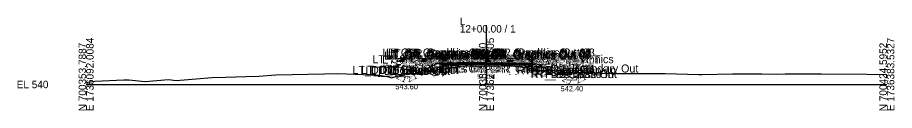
# Model space of a CAD drawing. Extents: x -26 to 697, y -10 to 2642.
# Drawn here: x -25.7 to 302.8, y 790.3 to 825 of the extents above; entities that cross this region are included whole.
import ezdxf

# ---------------------------------------------------------------- set-up
doc = ezdxf.new("R2010")
doc.units = 0
for name, color, linetype in [('Default', 7, 'Continuous'), ('Exist Cross Section Cell', 7, 'Continuous'), ('Exist XS Center Line Elevation Label', 7, 'Continuous'), ('Exist XS Ground Line', 7, 'Continuous'), ('Prop CMT Ditch DDE', 7, 'Continuous'), ('Prop CMT Guardrail Graphics', 7, 'Continuous'), ('Prop CMT Pvmt Course 1', 7, 'Continuous'), ('Prop CMT Pvmt Course 2', 7, 'Continuous'), ('Prop CMT Pvmt Surface', 7, 'Continuous'), ('Prop CMT Pvmt Surface Shoulder', 7, 'Continuous'), ('Prop CMT Shld Paved Course 1', 7, 'Continuous'), ('Prop CMT Shld Paved Course 2', 7, 'Continuous'), ('Prop CMT Slope Grass', 7, 'Continuous'), ('Prop CMT Subgrade Earthwork', 7, 'Continuous'), ('Prop XS Ditch Slope Text', 7, 'Continuous'), ('Prop XS Ditch Standard Text', 7, 'Continuous'), ('Prop XS SE Text', 7, 'Continuous'), ('Prop XS Side Slope Text', 7, 'Continuous')]:
    doc.layers.add(name, color=color, linetype=linetype)

msp = doc.modelspace()

# ---------------------------------------------------------------- linework, layer by layer
at = {"layer": 'Exist Cross Section Cell'}
for p, q in [((150, 800), (150, 822.2)), ((0, 800), (150, 800)), ((150, 800), (300, 800))]:
    msp.add_line(p, q, dxfattribs=at)
at = {"layer": 'Exist XS Ground Line'}
msp.add_lwpolyline([(0, 800.77), (3.26, 801.24), (14.09, 801.75), (16, 801.69), (22.08, 801.13), (30.89, 801.8), (33.77, 801.54), (41.24, 802.11), (47.09, 802.64), (52.16, 802.75), (59.97, 802.96), (64.67, 803.13), (71.03, 803.57), (89.36, 804), (94.3, 804.07), (97.52, 804), (109.9, 803.46), (113.46, 802.82), (114.25, 802.49), (120.37, 804.15), (121.19, 804.13), (124.03, 804.03), (124.71, 804.28), (125.87, 804.63), (128.83, 805.32), (132.7, 805.7), (134.61, 805.98), (136.73, 806.28), (140.54, 806.89), (144.86, 806.95), (149.69, 807), (150, 807), (159.67, 806.94), (160, 806.94), (160.56, 806.87), (164.49, 806.35), (167.73, 805.86), (170.77, 805.15), (172.35, 804.78), (173.05, 804.61), (175.25, 803.23), (177.12, 804.51), (181.98, 804.47), (188.77, 804.47), (192.71, 804.27), (198.65, 804.08), (209.91, 804.06), (216.94, 804.09), (229.51, 803.71), (230.75, 803.7), (242.11, 803.95), (253.15, 803.95), (258.48, 803.89), (261.9, 804), (271.23, 803.95), (274.36, 803.98), (275.49, 803.99), (292.51, 803.83), (300, 803.76)], dxfattribs=at)
at = {"layer": 'Prop CMT Ditch DDE'}
for points in [[(120.17, 803.6), (119.48, 803.94)], [(123.92, 804.03), (120.92, 803.97), (120.17, 803.6)], [(120.17, 803.6), (120.17, 803.6)], [(176.32, 803.91), (179.32, 803.85), (182.23, 802.4)], [(182.23, 802.4), (186.37, 804.47)], [(182.23, 802.4), (182.23, 802.4)]]:
    msp.add_lwpolyline(points, dxfattribs=at)
at = {"layer": 'Prop CMT Guardrail Graphics'}
for points in [[(132.65, 804.44), (132.65, 810.44)], [(132.65, 810.44), (133.98, 810.44), (134.25, 810.15)], [(134.25, 809.57), (133.98, 809.27), (133.31, 809.27)], [(133.31, 809.27), (133.31, 804.44)], [(134.25, 810.15), (133.98, 809.86)], [(133.98, 809.86), (134.25, 809.57)], [(167.35, 810.44), (166.02, 810.44), (165.75, 810.15)], [(165.75, 810.15), (166.02, 809.86)], [(166.02, 809.86), (165.75, 809.57)], [(165.75, 809.57), (166.02, 809.27), (166.69, 809.27)], [(166.69, 809.27), (166.69, 804.44)], [(167.35, 804.44), (167.35, 810.44)], [(133.31, 804.44), (132.65, 804.44)], [(166.69, 804.44), (167.35, 804.44)]]:
    msp.add_lwpolyline(points, dxfattribs=at)
at = {"layer": 'Prop CMT Pvmt Course 1'}
for points in [[(150, 808.26), (139, 808.04)], [(150, 808.05), (150, 808.26)], [(150, 808.26), (161, 808.04)], [(150, 808.05), (150, 808.26)], [(139, 807.83), (150, 808.05)], [(139, 808.04), (139, 807.83)], [(161, 807.83), (150, 808.05)], [(161, 808.04), (161, 807.83)]]:
    msp.add_lwpolyline(points, dxfattribs=at)
msp.add_lwpolyline([(150, 808.05), (150, 808.15), (150, 808.15), (150, 808.05)], close=True, dxfattribs=at)
msp.add_lwpolyline([(150, 808.05), (150, 808.15), (150, 808.15), (150, 808.05)], close=True, dxfattribs=at)
at = {"layer": 'Prop CMT Pvmt Course 2'}
for points in [[(150, 808.05), (139, 807.83)], [(139, 807.83), (139, 807.37)], [(139, 807.37), (150, 807.59)], [(150, 807.59), (150, 808.05)], [(150, 807.59), (150, 808.05)], [(150, 808.05), (161, 807.83)], [(161, 807.37), (150, 807.59)], [(161, 807.83), (161, 807.37)]]:
    msp.add_lwpolyline(points, dxfattribs=at)
at = {"layer": 'Prop CMT Pvmt Surface'}
for points in [[(150, 808.26), (139, 808.04)], [(150, 808.26), (161, 808.04)]]:
    msp.add_lwpolyline(points, dxfattribs=at)
at = {"layer": 'Prop CMT Pvmt Surface Shoulder'}
for points in [[(139, 808.04), (134.26, 807.94)], [(161, 808.04), (165.74, 807.94)]]:
    msp.add_lwpolyline(points, dxfattribs=at)
at = {"layer": 'Prop CMT Shld Paved Course 1'}
for points in [[(139, 808.04), (134.26, 807.94), (134.05, 807.73)], [(134.05, 807.73), (139, 807.83)], [(139, 807.83), (139, 808.04)], [(161, 808.04), (165.74, 807.94), (165.95, 807.73)], [(161, 807.83), (161, 808.04)], [(165.95, 807.73), (161, 807.83)]]:
    msp.add_lwpolyline(points, dxfattribs=at)
at = {"layer": 'Prop CMT Shld Paved Course 2'}
for points in [[(139, 807.83), (134.05, 807.73), (134.04, 807.73), (133.57, 807.26)], [(133.57, 807.26), (139, 807.37)], [(139, 807.37), (139, 807.83)], [(161, 807.83), (165.95, 807.73), (165.96, 807.73), (166.43, 807.26)], [(161, 807.37), (161, 807.83)], [(166.43, 807.26), (161, 807.37)]]:
    msp.add_lwpolyline(points, dxfattribs=at)
at = {"layer": 'Prop CMT Slope Grass'}
for points in [[(131.25, 807.7), (123.92, 804.03)], [(134.25, 807.94), (131.25, 807.7)], [(134.26, 807.94), (134.25, 807.94)], [(165.74, 807.94), (165.75, 807.94)], [(165.75, 807.94), (168.75, 807.7)], [(168.75, 807.7), (176.32, 803.91)]]:
    msp.add_lwpolyline(points, dxfattribs=at)
at = {"layer": 'Prop CMT Subgrade Earthwork'}
for points in [[(133.57, 807.26), (132.99, 807.84)], [(139, 807.37), (133.57, 807.26)], [(150, 807.59), (139, 807.37)], [(150, 807.59), (161, 807.37)], [(161, 807.37), (166.43, 807.26)], [(166.43, 807.26), (167.01, 807.84)]]:
    msp.add_lwpolyline(points, dxfattribs=at)

# ---------------------------------------------------------------- texts
at = {"layer": 'Default'}
for s, height, p in [('LT_GR_Graphics Out 03', 3, (111, 810.44)), ('LT_GR_Graphics Out 06', 3, (111.63, 809.27)), ('LT_GR_Graphics Out 07', 3, (112.26, 809.27)), ('LT_GR_Graphics Out 09', 3, (112.31, 809.86)), ('LT_GR_Graphics Out 02', 3, (112.39, 810.44)), ('LT_GR_Graphics Out 08', 3, (112.57, 809.57)), ('LT_GR_Graphics Out 01', 3, (113.09, 810.15)), ('RT_GR_Graphics Out 08', 3, (143.88, 809.57)), ('RT_GR_Graphics Out 07', 3, (144.12, 809.27)), ('RT_GR_Graphics Out 09', 3, (144.17, 809.86)), ('RT_GR_Graphics Out 02', 3, (144.25, 810.44)), ('RT_GR_Graphics Out 01', 3, (144.41, 810.15)), ('RT_GR_Graphics Out 06', 3, (144.83, 809.27)), ('RT_GR_Graphics Out 03', 3, (145.53, 810.44)), ('LT_GS_OS_GR_Face_Graphics', 3, (107.24, 807.94)), ('LT_Sub_Trench_Out_DLT', 3, (110.94, 807.84)), ('LT_Sub_Trench_Out', 3, (115.9, 807.26)), ('LT_GS_OS_CTL', 3, (117.64, 807.7)), ('LT_PS2_Shelf_Out', 3, (118.01, 807.73)), ('LT_PS2_OEOP', 3, (121.41, 807.73)), ('LT_PS1_OEOP', 3, (121.98, 807.94)), ('LT_PV2_OEOT', 3, (126.24, 807.83)), ('LT_Sub_OEOT', 3, (126.31, 807.37)), ('LT_PV1_OEOT', 3, (126.6, 808.04)), ('RT_PV2_OEEOP', 3, (136, 808.05)), ('RT_Sub_OEEOP', 3, (136.07, 807.59)), ('LT_PV2_OEEOP', 3, (136.18, 808.05)), ('LT_Sub_OEEOP', 3, (136.25, 807.59)), ('RT_PV1_OEEOP', 3, (136.36, 808.15)), ('LT_PV1_OEEOP', 3, (136.54, 808.15)), ('RT_PV2_IEEOP', 3, (137.14, 808.05)), ('LT_PV2_IEEOP', 3, (137.32, 808.05)), ('RT_PV1_IEEOP', 3, (137.5, 808.15)), ('LT_PV1_IEEOP', 3, (137.68, 808.15)), ('RT_GS_OS_GR_Face_Graphics', 3, (138.56, 807.94)), ('PV2_PGL', 3, (142.05, 808.05)), ('PV1_PGL', 3, (142.41, 808.26)), ('RT_Sub_Trench_Out_DLT', 3, (144.78, 807.84)), ('RT_PV2_OEOT', 3, (148.06, 807.83)), ('RT_Sub_OEOT', 3, (148.13, 807.37)), ('RT_PV1_OEOT', 3, (148.42, 808.04)), ('RT_Sub_Trench_Out', 3, (148.58, 807.26)), ('RT_PS2_Shelf_Out', 3, (149.75, 807.73)), ('RT_PS2_OEOP', 3, (153.13, 807.73)), ('RT_PS1_OEOP', 3, (153.28, 807.94)), ('RT_GS_OS_CTL', 3, (154.96, 807.7)), ('LT_DD_Boundary Out', 3, (99.82, 803.94)), ('LT_DD_Boundary In', 3, (103.09, 803.97)), ('LT_DD_Base Out', 3, (104.67, 803.6)), ('LT_DD_Base In', 3, (106.51, 803.6)), ('LT_GR_Graphics Out 04', 3, (110.96, 804.44)), ('LT_GR_Graphics Out 05', 3, (111.65, 804.44)), ('LT_Slope_Fill', 3, (112.63, 804.03)), ('LT_Slope_Fill', 3, (112.63, 804.03)), ('RT_GR_Graphics Out 05', 3, (144.84, 804.44)), ('RT_GR_Graphics Out 04', 3, (145.48, 804.44)), ('RT_DD_Boundary In', 3, (161.32, 803.85)), ('RT_Slope_Fill', 3, (164.86, 803.91)), ('RT_Slope_Fill', 3, (164.86, 803.91)), ('RT_DD_Boundary Out', 3, (166.53, 804.47)), ('RT_DD_Base Out', 3, (166.55, 802.4)), ('RT_DD_Base In', 3, (168.39, 802.4)), ('-', 0.0001, (0, 800))]:
    msp.add_text(s, height=height, dxfattribs=at).set_placement(p)
at = {"layer": 'Exist Cross Section Cell'}
for s, p in [('L', (140, 822.2)), ('12+00.00 / 1', (140, 819.4)), ('EL 540', (-26, 798.6))]:
    msp.add_text(s, height=2.8, dxfattribs=at).set_placement(p)
for s, p in [('N 700353.7887', (0, 790)), ('E 1736092.0084', (2.8, 790)), ('N 700389.1920', (150, 790)), ('E 1736237.7705', (152.8, 790)), ('N 700424.5952', (300, 790)), ('E 1736383.5327', (302.8, 790))]:
    msp.add_text(s, height=2.8, rotation=90, dxfattribs=at).set_placement(p)
at = {"layer": 'Exist XS Center Line Elevation Label'}
msp.add_text('547.00', height=1.6, dxfattribs=at).set_placement((146.57, 802.2))
at = {"layer": 'Prop XS Ditch Slope Text'}
for rotation, p in [(333.4349, (115.98, 802.37)), (26.5651, (120.84, 800.72)), (333.4349, (178.13, 801.38)), (26.5651, (184.11, 800.27))]:
    msp.add_text('2:1', height=2, rotation=rotation, dxfattribs=at).set_placement(p)
at = {"layer": 'Prop XS Ditch Standard Text'}
for s, p in [('543.60', (115.85, 798.21)), ('542.40', (177.78, 797.44))]:
    msp.add_text(s, height=2, dxfattribs=at).set_placement(p)
at = {"layer": 'Prop XS SE Text'}
for rotation, p in [(1.1458, (140.98, 809.08)), (358.8542, (152.02, 809.22))]:
    msp.add_text('0.020', height=2, rotation=rotation, dxfattribs=at).set_placement(p)
at = {"layer": 'Prop XS Side Slope Text'}
for rotation, p in [(26.5635, (125.83, 805.83)), (333.4349, (171.45, 807.19))]:
    msp.add_text('2:1', height=2, rotation=rotation, dxfattribs=at).set_placement(p)

doc.saveas('drawing.dxf')
